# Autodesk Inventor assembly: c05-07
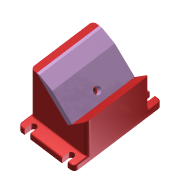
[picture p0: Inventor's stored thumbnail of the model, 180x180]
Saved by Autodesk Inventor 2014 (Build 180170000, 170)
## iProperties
Created: 2010-11
Part Number: c05-07
Document SubType Name: Assembly
Designer: Thom Tremblay
Author: Thom Tremblay
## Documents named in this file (3)
- C:\Inventor 2014 Essentials\Assemblies\Chapter 05\c05-07.iam
- C:\Inventor 2014 Essentials\Parts\Chapter 05\c05-03.ipt
- C:\Inventor 2014 Essentials\Parts\Chapter 05\c05-04.ipt
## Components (2 placed, 2 different names)
1. c05-03:1 — Insert:1, Angle:1
2. c05-04:1 — Insert:1, Angle:1
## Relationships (2: Insert 1, Angle 1)
- Insert:1: c05-03:1 ↔ c05-04:1
- Angle:1: c05-03:1 ↔ c05-04:1
